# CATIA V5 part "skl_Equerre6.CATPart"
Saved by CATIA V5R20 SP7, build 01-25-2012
Part number: skl_Equerre6
Publications: "Axe_Equerre6Patin2", "Axe_Equerre6Socle", "Axe_Equerre6Bielle4", "Point.1", "Point.2", "Point.3", "Plan.1", "Corps principal"
Bounding box of the stored display mesh (mm): x 0 to 20, y 10.033 to 47, z 111 to 134.34
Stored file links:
  J:\ACHTUNG2\skl_Equerre6.CATPart
  J:\cmilovidofIAO\skl_IAO.CATProduct
  C:\Users\Cedric\Desktop\ifma\Fichier S3\IAO\Equerre.CATPart
  J:\ACHTUNG2\skl_IAO2.CATProduct
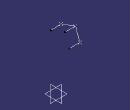
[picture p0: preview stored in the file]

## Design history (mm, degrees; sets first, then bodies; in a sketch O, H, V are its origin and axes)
Set1
  Point1 to Point3: linked copy from another document
  Plane1: linked copy from another document
Body1 (main body)
  Line1: type PtPt, FirstPoint Point1, SecondPoint Point2
  Line2: type PtPt, FirstPoint Point3, SecondPoint Point1
  Line3: type Normal, RefPoint Point2, RefSkin Plane1, Start 0, End 20
  Line4: type Normal, RefPoint Point1, RefSkin Plane1, Start 0, End 20
  Line5: type Normal, RefPoint Point3, RefSkin Plane1, Start 0, End 20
